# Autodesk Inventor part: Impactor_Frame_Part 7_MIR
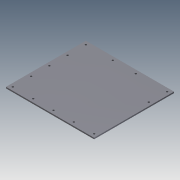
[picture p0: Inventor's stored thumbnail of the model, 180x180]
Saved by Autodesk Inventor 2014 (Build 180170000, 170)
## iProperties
Created: 2012-08
Part Number: Impactor_Frame_Part 7_MIR
Material: Steel, Mild
Document SubType Name: Modeling
Designer: mike.van voorhis
Density: 7.86 g/cm^3
Appearance: Steel
Author: mike.van voorhis
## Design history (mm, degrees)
derived "Impactor_Frame_Part 7.ipt"
  sketch "Sketch1"
    geometry: L1 (0, 0)-(-644.525, 0) reference; L2 (-644.525, 0)-(-644.525, 9.525) reference; L3 (-644.525, 9.525)-(0, 9.525) reference; L4 (0, 9.525)-(0, 0) reference
  sketch "Sketch2"
    geometry: L1 (0, 0)-(0, 584.2) reference; L2 (-644.525, 0)-(-644.525, 584.2) reference; L3 (0, 25.4)-(-25.4, 25.4) reference; L4 (-25.4, 25.4)-(-25.4, 158.75) reference; L5 (-25.4, 158.75)-(-25.4, 292.1) reference; L6 (-25.4, 292.1)-(-25.4, 425.45) reference; L7 (-25.4, 425.45)-(-25.4, 558.8) reference; L8 (-25.4, 25.4)-(-222.25, 25.4) reference; L9 (-644.525, 25.4)-(-619.125, 25.4) reference; L10 (-619.125, 25.4)-(-390.525, 25.4) reference; L11 (-619.125, 25.4)-(-619.125, 158.75) reference; L12 (-619.125, 158.75)-(-619.125, 292.1) reference; L13 (-619.125, 292.1)-(-619.125, 425.45) reference; L14 (-619.125, 425.45)-(-619.125, 558.8) reference; L15 (-25.4, 558.8)-(-173.831, 558.8) reference; L16 (-173.831, 558.8)-(-322.262, 558.8) reference; L17 (-322.262, 558.8)-(-470.694, 558.8) reference; C1 r 6.747 at (-25.4, 25.4) reference; C2 r 6.747 at (-25.4, 158.75) reference; C3 r 6.747 at (-25.4, 292.1) reference; C4 r 6.747 at (-25.4, 425.45) reference; C5 r 6.747 at (-25.4, 558.8) reference; C6 r 6.747 at (-619.125, 25.4) reference; C7 r 6.747 at (-390.525, 25.4) reference; C8 r 6.747 at (-222.25, 25.4) reference; C9 r 6.747 at (-619.125, 158.75) reference; C10 r 6.747 at (-619.125, 558.8) reference; C11 r 6.747 at (-173.831, 558.8) reference; C12 r 6.747 at (-322.262, 558.8) reference; C13 r 6.747 at (-470.694, 558.8) reference
feature "Solid1::Impactor_Frame_Part 7.ipt" dims "d0" = 10
tag "TaggingFeature1"
body "Solid1"
